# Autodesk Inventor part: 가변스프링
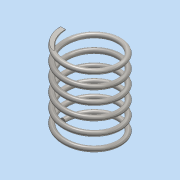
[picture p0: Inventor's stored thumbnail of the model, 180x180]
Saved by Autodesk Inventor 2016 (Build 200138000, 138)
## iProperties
Created: 2018-11
Part Number: 가변스프링
Material: 스테인레스 스틸
Document SubType Name: Modeling
Designer: user
Density: 8 g/cm^3
Appearance: 반연마
Mass: 84.1985 g
Surface Area: 106.476 cm^2
Volume: 10.5248 cm^3
Author: user
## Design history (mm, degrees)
sketch "스케치1"
  geometry: L1 (0, 0)-(22.5, 0); L2 (22.5, 0)-(22.5, 67.25); L3 (22.5, 67.25)-(0, 67.25); L4 (0, 67.25)-(0, 0); C1 r 2 at (22.5, 0)
  constraints: 8 end point, 2 parallel, 1 centre point, 1 coincident, 1 horizontal, 1 perpendicular
  dimensions: "d0" = 67.25 distance of L3.end L1.start (derived); "d1" = 4 diameter of C1; "d2" = 45 diameter of L2 L4
feature "코일1" sketch "스케치1" pitch "d3" = 10; turns "d5" = 6; dims "d4" = 67.25 (= d0), "d6" = 0, angle "d7" = 90 deg, angle "d8" = 90 deg, "d9" = 0, "d10" = 0
sketch "스케치2"
  geometry: L1 (84.1, 67.25)-(-84.1, 67.25); L2 (-84.1, 67.25)-(-84.1, 0); L3 (-84.1, 0)-(84.1, 0); L4 (84.1, 0)-(84.1, 67.25); 2 further points
  constraints: 8 end point, 2 parallel, 1 coincident, 1 horizontal, 1 midpoint, 1 perpendicular
  dimensions: "d11" = 168.19974 distance between parallel lines of L2 L4; "d12" = 67.25 distance between parallel lines of L3 L1 (= d0)
extrude "돌출1" sketch "스케치2" stored distance "d13" = 100; taper "d14" = 0 deg
node "솔리드1"
